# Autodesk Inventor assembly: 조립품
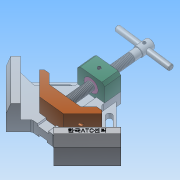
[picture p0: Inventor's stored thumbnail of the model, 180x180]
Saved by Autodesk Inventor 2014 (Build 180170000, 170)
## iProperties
Created: 2020-05
Part Number: 조립품
Document SubType Name: Assembly
Designer: NET
Author: NET
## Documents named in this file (11)
- C:\Users\NET\Desktop\700506V1002\조립품.iam
- C:\Users\NET\Desktop\700506V1002\베이스.ipt
- C:\Users\NET\Desktop\700506V1002\리드스크류.ipt
- C:\Users\NET\Desktop\700506V1002\멈춤나사 M4x5.ipt
- C:\Users\NET\Desktop\700506V1002\멈춤나사 M4x10.ipt
- C:\Users\NET\Desktop\700506V1002\볼트 M4x16.ipt
- C:\Users\NET\Desktop\700506V1002\부시.ipt
- C:\Users\NET\Desktop\700506V1002\서포트.ipt
- C:\Users\NET\Desktop\700506V1002\조.ipt
- C:\Users\NET\Desktop\700506V1002\평행 핀 2.5x24.ipt
- C:\Users\NET\Desktop\700506V1002\핸들.ipt
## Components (1 placed, 1 different names)
1. 핸들:1
